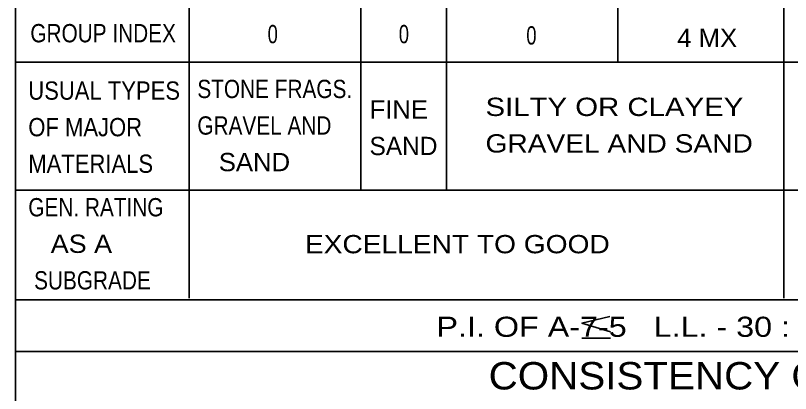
# Model space of a CAD drawing. Extents: x 2137492.6 to 2137529.1, y 2137475.8 to 2137563.
# Drawn here: x 2137493.171 to 2137497.407, y 2137551.11 to 2137553.178 of the extents above; entities that cross this region are included whole.
import ezdxf
from ezdxf.enums import TextEntityAlignment as Align

# ---------------------------------------------------------------- set-up
doc = ezdxf.new("R2010")
doc.units = 0
doc.header["$LTSCALE"] = 0.04
doc.layers.add('1', color=7, linetype='Continuous', lineweight=35)

msp = doc.modelspace()

# ---------------------------------------------------------------- linework, layer by layer
at = {"layer": '1'}
for p, q in [((2137494.121, 2137556.123), (2137494.121, 2137551.631)), ((2137497.371, 2137556.123), (2137497.371, 2137551.631)), ((2137495.059, 2137552.223), (2137495.059, 2137555.621)), ((2137495.527, 2137552.223), (2137495.527, 2137555.621)), ((2137496.463, 2137552.923), (2137496.463, 2137555.374)), ((2137493.171, 2137552.923), (2137499.271, 2137552.923)), ((2137493.171, 2137552.223), (2137501.871, 2137552.223)), ((2137493.171, 2137551.623), (2137501.871, 2137551.623)), ((2137496.266, 2137551.413), (2137496.423, 2137551.413)), ((2137510.771, 2137551.34), (2137493.171, 2137551.34))]:
    msp.add_line(p, q, dxfattribs=at)
for points in [[(2137493.171, 2137561.718), (2137493.171, 2137539.727), (2137528.371, 2137539.727)], [(2137496.42, 2137551.531), (2137496.267, 2137551.495), (2137496.424, 2137551.447)]]:
    msp.add_lwpolyline(points, dxfattribs=at)

# ---------------------------------------------------------------- texts
for s, height, width, p in [('GROUP INDEX', 0.1, 0.85, (2137493.65, 2137553.031)), ('0', 0.1, 0.75, (2137494.577, 2137553.026)), ('0', 0.1, 0.75, (2137495.294, 2137553.026)), ('0', 0.1, 0.75, (2137495.991, 2137553.019)), ('4 MX', 0.1, 1.05, (2137496.9515, 2137553.005)), ('EXCELLENT TO GOOD', 0.1, 1.15, (2137495.586, 2137551.877)), ('P.I. OF A-7-5   L.L. - 30 : P.I. OF A-7-6   L.L. - 30', 0.11, 1.2, (2137497.38, 2137551.42))]:
    msp.add_text(s, height=height, dxfattribs=dict(at, width=width)).set_placement(p, align=Align.CENTER)
for s, height, width, p in [('USUAL TYPES', 0.1, 0.9, (2137493.241, 2137552.717)), ('STONE FRAGS.', 0.1, 0.85, (2137494.165, 2137552.726)), ('FINE', 0.1, 1.05, (2137495.106, 2137552.614)), ('SILTY OR CLAYEY', 0.1, 1.2, (2137495.74, 2137552.628)), ('OF MAJOR', 0.1, 0.9, (2137493.241, 2137552.517)), ('GRAVEL AND', 0.1, 0.85, (2137494.165, 2137552.526)), ('GRAVEL AND SAND', 0.1, 1.15, (2137495.74, 2137552.428)), ('MATERIALS', 0.1, 0.9, (2137493.241, 2137552.317)), ('   SAND', 0.1, 1.05, (2137494.165, 2137552.326)), ('GEN. RATING', 0.1, 0.85, (2137493.241, 2137552.079)), ('   AS A', 0.1, 1.1, (2137493.241, 2137551.879)), (' SUBGRADE', 0.1, 0.85, (2137493.241, 2137551.679)), ('CONSISTENCY OR DENSENESS', 0.15, 1.1, (2137495.757, 2137551.132))]:
    msp.add_text(s, height=height, dxfattribs=dict(at, width=width)).set_placement(p)
msp.add_text('SAND', height=0.1, dxfattribs=at).set_placement((2137495.106, 2137552.414))

doc.saveas('drawing.dxf')
